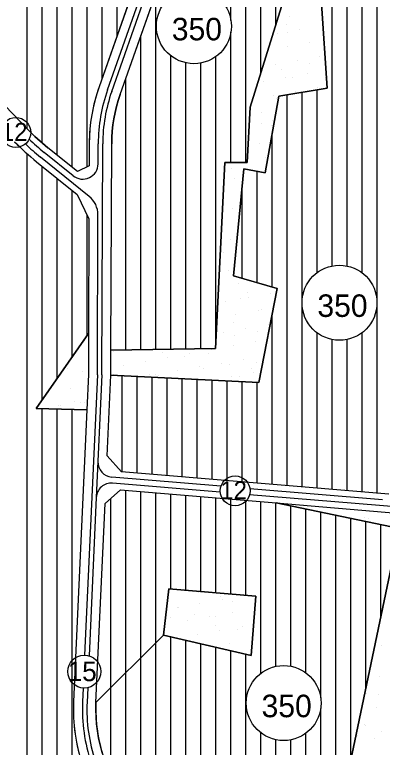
# Model space of a CAD drawing. Extents: x 419109 to 421295, y 4452223 to 4457798.
# Drawn here: x 420679.4 to 420924.6, y 4452952.7 to 4453441.3 of the extents above; entities that cross this region are included whole.
import ezdxf

# ---------------------------------------------------------------- set-up
doc = ezdxf.new("R2010")
doc.units = 0
for name, color, linetype in [('ADA', 7, 'Continuous'), ('ADAKENARI', 7, 'Continuous'), ('Default', 7, 'Continuous'), ('KALDIRIM', 7, 'Continuous'), ('KD_DAIRE', 7, 'Continuous'), ('KD_YGEN', 7, 'Continuous'), ('PL_AYA_PARK_DINLENME', 7, 'Continuous'), ('PL_KON_MEV_350', 7, 'Continuous'), ('SM_DAIRE', 7, 'Continuous'), ('SM_TAKS', 7, 'Continuous'), ('TR_ORTAYOGUNKONUT', 7, 'Continuous'), ('TR_PARKALANI', 7, 'Continuous')]:
    doc.layers.add(name, color=color, linetype=linetype)

# ---------------------------------------------------------------- blocks, each defined once
blk = doc.blocks.new('POINT_DISPLAY')
at = {"layer": 'Default'}
blk.add_line((0, 0), (0, 0), dxfattribs=at)

msp = doc.modelspace()

# ---------------------------------------------------------------- linework, layer by layer
at = {"layer": 'ADA'}
for p, q in [((420901.28, 4453588.27), (420836.55, 4453379.63)), ((420887.76, 4453392.3), (420884.07, 4453448.79)), ((420855.56, 4453387.02), (420887.76, 4453392.3)), ((420846.58, 4453335.82), (420855.56, 4453387.02)), ((420836.55, 4453379.63), (420834.44, 4453342.68)), ((420819.66, 4453342.68), (420813.32, 4453218.61)), ((420834.44, 4453342.68), (420819.66, 4453342.68)), ((420825.47, 4453267.18), (420832.33, 4453338.45)), ((420832.33, 4453338.45), (420846.58, 4453335.82)), ((420854.5, 4453258.74), (420825.47, 4453267.18)), ((420842.36, 4453195.91), (420854.5, 4453258.74)), ((420728.7, 4453228.73), (420693.82, 4453178.65)), ((420813.32, 4453218.61), (420743.66, 4453217.53)), ((420743.6, 4453200.88), (420842.36, 4453195.91)), ((420693.82, 4453178.65), (420727.53, 4453177.73)), ((420936.03, 4453098.7), (420853.73, 4453115.66)), ((420903.28, 4452943.11), (420930.77, 4453073.67)), ((420778.66, 4453027.49), (420782.22, 4453058.47)), ((420782.22, 4453058.47), (420840.26, 4453053.48)), ((420840.26, 4453053.48), (420837.05, 4453013.96)), ((420837.05, 4453013.96), (420778.66, 4453027.49))]:
    msp.add_line(p, q, dxfattribs=at)
at = {"layer": 'ADAKENARI'}
for p, q in [((420814.22, 4453615.89), (420735.68, 4453393.04)), ((420749.83, 4453388.06), (420826.37, 4453605.23)), ((420688.05, 4453364.9), (420668.06, 4453385.54)), ((420729.14, 4453355.22), (420729.09, 4453340.38)), ((420743.66, 4453217.53), (420744.14, 4453355.17)), ((420721.27, 4453336.66), (420701.59, 4453352.54)), ((420694.05, 4453343.2), (420721.22, 4453321.28)), ((420729.09, 4453340.38), (420721.27, 4453336.66)), ((420721.22, 4453321.28), (420728.97, 4453305)), ((420728.97, 4453305), (420728.7, 4453228.73)), ((420728.7, 4453228.73), (420728.6, 4453201.25)), ((420743.6, 4453200.88), (420743.66, 4453217.53)), ((420728.6, 4453201.25), (420727.53, 4453177.73)), ((420741.16, 4453147.16), (420743.6, 4453200.88)), ((420727.53, 4453177.73), (420718.69, 4452983.19)), ((420750.67, 4453136.33), (420741.16, 4453147.16)), ((420928.94, 4453121.4), (420750.67, 4453136.33)), ((420739.7, 4453115.18), (420750.12, 4453124.34)), ((420750.12, 4453124.34), (420853.73, 4453115.66)), ((420733.67, 4452982.51), (420739.7, 4453115.18)), ((420853.73, 4453115.66), (420934.35, 4453108.91))]:
    msp.add_line(p, q, dxfattribs=at)
for centre, radius, start, end in [((420844.14, 4453354.81), 115, 160.5853, 179.7987), ((420844.14, 4453354.81), 100, 160.5853, 179.7987), ((420795.79, 4453469.27), 150, 224.0912, 231.0974), ((420795.79, 4453469.27), 162, 224.0912, 231.0974), ((420833.57, 4452977.97), 115, 177.3972, 199.0423), ((420833.57, 4452977.97), 100, 177.3972, 199.0423)]:
    msp.add_arc(centre, radius, start, end, dxfattribs=at)
at = {"layer": 'KALDIRIM'}
for p, q in [((420741.34, 4453391.05), (420765.66, 4453460.05)), ((420744.17, 4453390.05), (420768.35, 4453458.65)), ((420735.1, 4453341.79), (420735.14, 4453355.2)), ((420737.6, 4453201.03), (420738.14, 4453355.19)), ((420718.39, 4453333.84), (420699.08, 4453349.43)), ((420729.12, 4453320.04), (420696.56, 4453346.32)), ((420734.6, 4453201.1), (420734.98, 4453307.74)), ((420734.6, 4453201.1), (420726.1, 4453014.19)), ((420737.6, 4453201.03), (420733.88, 4453119.29)), ((420816.95, 4453126.77), (420744.13, 4453132.87)), ((420816.51, 4453122.79), (420744.71, 4453128.8)), ((420924.61, 4453117.75), (420836.36, 4453125.14)), ((420733.88, 4453119.29), (420729.09, 4453013.72)), ((420936.62, 4453112.73), (420836.13, 4453121.15)), ((420725.11, 4452992.22), (420724.68, 4452982.92)), ((420728.12, 4452992.42), (420727.68, 4452982.78))]:
    msp.add_line(p, q, dxfattribs=at)
for centre, radius, start, end in [((420844.14, 4453354.81), 109, 160.5853, 179.7987), ((420844.14, 4453354.81), 106, 160.5853, 179.7987), ((420795.79, 4453469.27), 158, 226.2962, 231.0974), ((420795.79, 4453469.27), 154, 226.1558, 231.0974), ((420724.84, 4453341.83), 10.26, 231.0974, 359.7987), ((420719.25, 4453307.8), 15.73, 359.7987, 51.0974), ((420744.97, 4453142.83), 10, 177.3972, 265.212), ((420743.87, 4453118.84), 10, 85.212, 177.3972), ((420833.57, 4452977.97), 109, 177.3972, 199.0423), ((420833.57, 4452977.97), 106, 177.3972, 199.0423)]:
    msp.add_arc(centre, radius, start, end, dxfattribs=at)
at = {"layer": 'KD_DAIRE'}
for centre, radius in [((420680.18, 4453362.7), 10), ((420826.47, 4453123.71), 10), ((420725.89, 4453003.19), 11)]:
    msp.add_circle(centre, radius, dxfattribs=at)
at = {"layer": 'PL_AYA_PARK_DINLENME'}
for points in [[(420836.55, 4453379.63), (420901.28, 4453588.27), (420939.56, 4453574.15), (420903.07, 4453570.75), (420888.82, 4453532.21), (420893.04, 4453450.38), (420884.07, 4453448.79), (420887.76, 4453392.3), (420855.56, 4453387.02), (420846.58, 4453335.82), (420832.33, 4453338.45), (420825.47, 4453267.18), (420854.5, 4453258.74), (420842.36, 4453195.91), (420743.6, 4453200.88), (420743.66, 4453217.53), (420813.32, 4453218.61), (420819.66, 4453342.68), (420834.44, 4453342.68)], [(420727.53, 4453177.73), (420693.82, 4453178.65), (420728.7, 4453228.73), (420728.6, 4453201.25)], [(420936.03, 4453098.7), (420853.73, 4453115.66), (420934.35, 4453108.91), (420949.33, 4453099.42), (420951.61, 4453095.49)], [(420903.28, 4452943.11), (420930.77, 4453073.67), (420951.34, 4453069.86), (420962.86, 4453076.1), (420986.96, 4453034.57), (420939.24, 4453034.97), (420937.46, 4452935.63)], [(420837.05, 4453013.96), (420778.66, 4453027.49), (420782.22, 4453058.47), (420840.26, 4453053.48)]]:
    msp.add_lwpolyline(points, close=True, dxfattribs=at)
at = {"layer": 'PL_KON_MEV_350'}
for points in [[(420814.22, 4453615.89), (420735.68, 4453393.04), (420734.17, 4453388.46), (420732.86, 4453383.82), (420731.74, 4453379.14), (420730.82, 4453374.4), (420730.1, 4453369.64), (420729.58, 4453364.85), (420729.26, 4453360.04), (420729.14, 4453355.22), (420729.09, 4453340.38), (420721.27, 4453336.66), (420701.59, 4453352.54), (420699.81, 4453353.99), (420698.06, 4453355.48), (420696.34, 4453356.98), (420694.63, 4453358.52), (420692.95, 4453360.07), (420691.29, 4453361.66), (420689.66, 4453363.27), (420688.05, 4453364.9), (420668.06, 4453385.54)], [(420928.94, 4453121.4), (420750.67, 4453136.33), (420741.16, 4453147.16), (420743.6, 4453200.88), (420842.36, 4453195.91), (420854.5, 4453258.74), (420825.47, 4453267.18), (420832.33, 4453338.45), (420846.58, 4453335.82), (420855.56, 4453387.02), (420887.76, 4453392.3), (420884.07, 4453448.79)], [(420679.43, 4453356.55), (420681.17, 4453354.79), (420682.93, 4453353.05), (420684.72, 4453351.34), (420686.54, 4453349.65), (420688.38, 4453348), (420690.25, 4453346.37), (420692.14, 4453344.77), (420694.05, 4453343.2), (420721.22, 4453321.28), (420728.97, 4453305), (420728.7, 4453228.73), (420693.82, 4453178.65), (420727.53, 4453177.73), (420718.69, 4452983.19), (420718.57, 4452977.76), (420718.71, 4452972.33), (420719.1, 4452966.91), (420719.75, 4452961.52), (420720.65, 4452956.17), (420721.81, 4452950.86)]]:
    msp.add_lwpolyline(points, dxfattribs=at)
for points in [[(420749.83, 4453388.06), (420826.37, 4453605.23), (420839.08, 4453611.2), (420901.28, 4453588.27), (420836.55, 4453379.63), (420834.44, 4453342.68), (420819.66, 4453342.68), (420813.32, 4453218.61), (420743.66, 4453217.53), (420744.14, 4453355.17), (420744.24, 4453359.36), (420744.52, 4453363.54), (420744.98, 4453367.71), (420745.6, 4453371.85), (420746.4, 4453375.96), (420747.38, 4453380.04), (420748.52, 4453384.07)], [(420853.73, 4453115.66), (420936.03, 4453098.7), (420930.77, 4453073.67), (420903.28, 4452943.11), (420896.71, 4452915.75), (420797.89, 4452939.65), (420762.79, 4452946.51), (420739.04, 4452945.34), (420737.61, 4452949.84), (420736.39, 4452954.4), (420735.38, 4452959.01), (420734.6, 4452963.67), (420734.03, 4452968.36), (420733.69, 4452973.07), (420733.57, 4452977.79), (420733.67, 4452982.51), (420778.66, 4453027.49), (420837.05, 4453013.96), (420840.26, 4453053.48), (420782.22, 4453058.47), (420778.66, 4453027.49), (420733.67, 4452982.51), (420739.7, 4453115.18), (420750.12, 4453124.34)]]:
    msp.add_lwpolyline(points, close=True, dxfattribs=at)
at = {"layer": 'SM_DAIRE'}
for centre in [(420798.96, 4453433.58), (420896.04, 4453249.15), (420858.83, 4452982.2)]:
    msp.add_circle(centre, 25, dxfattribs=at)
at = {"layer": 'TR_ORTAYOGUNKONUT'}
for p, q in [((420747.76, 4453427.31), (420747.76, 4453678.84)), ((420737.76, 4453398.94), (420737.76, 4453666.77)), ((420833.66, 4453342.68), (420833.66, 4453608.65)), ((420843.66, 4453402.54), (420843.66, 4453609.51)), ((420853.66, 4453434.77), (420853.66, 4453605.82)), ((420823.66, 4453437.48), (420823.66, 4453597.54)), ((420911.16, 4453269.06), (420911.16, 4453571.5)), ((420921.16, 4453122.05), (420921.16, 4453572.43)), ((420901.16, 4453273.62), (420901.16, 4453565.57)), ((420687.76, 4453365.21), (420687.76, 4453496.6)), ((420727.76, 4453339.74), (420727.76, 4453499.32)), ((420697.76, 4453355.74), (420697.76, 4453489.53)), ((420707.76, 4453347.56), (420707.76, 4453487.88)), ((420717.76, 4453339.49), (420717.76, 4453490.42)), ((420773.66, 4453218), (420773.66, 4453455.67)), ((420891.16, 4453273.67), (420891.16, 4453450.04)), ((420763.66, 4453217.84), (420763.66, 4453427.3)), ((420823.66, 4453342.68), (420823.66, 4453429.68)), ((420783.66, 4453218.15), (420783.66, 4453413.82)), ((420813.66, 4453225.18), (420813.66, 4453413.36)), ((420793.66, 4453218.31), (420793.66, 4453409.15)), ((420803.66, 4453218.46), (420803.66, 4453409.03)), ((420753.66, 4453217.69), (420753.66, 4453398.92)), ((420861.16, 4453127.08), (420861.16, 4453387.94)), ((420871.16, 4453251.6), (420871.16, 4453389.58)), ((420881.16, 4453269.24), (420881.16, 4453391.22)), ((420851.16, 4453259.71), (420851.16, 4453361.92)), ((420687.83, 4452920.69), (420687.83, 4453348.49)), ((420697.83, 4453184.41), (420697.83, 4453340.15)), ((420841.16, 4453262.62), (420841.16, 4453336.82)), ((420707.83, 4453198.77), (420707.83, 4453332.08)), ((420831.16, 4453265.53), (420831.16, 4453326.29)), ((420717.83, 4453213.13), (420717.83, 4453324.01)), ((420727.83, 4453227.49), (420727.83, 4453307.38)), ((420871.16, 4453126.24), (420871.16, 4453246.69)), ((420851.16, 4453127.92), (420851.16, 4453241.43)), ((420881.16, 4453125.4), (420881.16, 4453229.06)), ((420911.16, 4453122.89), (420911.16, 4453229.24)), ((420891.16, 4453124.57), (420891.16, 4453224.63)), ((420901.16, 4453123.73), (420901.16, 4453224.68)), ((420751.16, 4453136.29), (420751.16, 4453200.5)), ((420761.16, 4453135.45), (420761.16, 4453200)), ((420771.16, 4453134.62), (420771.16, 4453199.5)), ((420781.16, 4453133.78), (420781.16, 4453198.99)), ((420791.16, 4453132.94), (420791.16, 4453198.49)), ((420801.16, 4453132.1), (420801.16, 4453197.99)), ((420811.16, 4453131.27), (420811.16, 4453197.48)), ((420821.16, 4453130.43), (420821.16, 4453196.98)), ((420831.16, 4453129.59), (420831.16, 4453196.48)), ((420841.16, 4453128.75), (420841.16, 4453195.97)), ((420697.83, 4452918.49), (420697.83, 4453178.54)), ((420707.83, 4452916.28), (420707.83, 4453178.27)), ((420717.83, 4452914.09), (420717.83, 4453177.99)), ((420753.57, 4452946.06), (420753.57, 4453124.05)), ((420763.57, 4452946.36), (420763.57, 4453123.21)), ((420773.57, 4452944.4), (420773.57, 4453122.37)), ((420783.57, 4453058.35), (420783.57, 4453121.54)), ((420793.57, 4453057.49), (420793.57, 4453120.7)), ((420803.57, 4453056.63), (420803.57, 4453119.86)), ((420743.57, 4452945.56), (420743.57, 4453118.58)), ((420813.57, 4453055.77), (420813.57, 4453119.02)), ((420823.57, 4453054.91), (420823.57, 4453118.18)), ((420833.57, 4453054.06), (420833.57, 4453117.35)), ((420843.57, 4453002), (420843.57, 4453116.51)), ((420853.57, 4453006.64), (420853.57, 4453115.67)), ((420863.57, 4453006.74), (420863.57, 4453113.63)), ((420873.57, 4453002.39), (420873.57, 4453111.57)), ((420883.57, 4452985.77), (420883.57, 4453109.51)), ((420893.57, 4452921.26), (420893.57, 4453107.45)), ((420903.57, 4452944.49), (420903.57, 4453105.39)), ((420913.57, 4452991.99), (420913.57, 4453103.33)), ((420923.57, 4453039.49), (420923.57, 4453101.27)), ((420783.57, 4452942.45), (420783.57, 4453026.35)), ((420793.57, 4452940.49), (420793.57, 4453024.03)), ((420803.57, 4452938.27), (420803.57, 4453021.72)), ((420813.57, 4452935.85), (420813.57, 4453019.4)), ((420823.57, 4452933.44), (420823.57, 4453017.08)), ((420833.57, 4452931.02), (420833.57, 4453014.77)), ((420883.57, 4452928.34), (420883.57, 4452978.63)), ((420843.57, 4452928.6), (420843.57, 4452962.39)), ((420873.57, 4452930), (420873.57, 4452962.01)), ((420853.57, 4452926.18), (420853.57, 4452957.76)), ((420863.57, 4452927.47), (420863.57, 4452957.65))]:
    msp.add_line(p, q, dxfattribs=at)

# ---------------------------------------------------------------- block references
at = {"layer": 'TR_PARKALANI', "xscale": 0.1, "yscale": 0.10000000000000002}
for p in [(420862.97, 4453440.35), (420860.65, 4453434.93), (420884.4, 4453433.98), (420854.86, 4453428.77), (420861.53, 4453429.47), (420869.63, 4453431.37), (420885, 4453429.25), (420876.29, 4453422.39), (420861.52, 4453419.79), (420882.95, 4453413.41), (420853.4, 4453408.21), (420868.18, 4453410.81), (420876.1, 4453408.74), (420857.19, 4453404.85), (420860.06, 4453399.23), (420864.61, 4453399.09), (420874.84, 4453401.83), (420886.73, 4453399.64), (420845.29, 4453396.62), (420881.5, 4453392.85), (420866.73, 4453390.25), (420851.95, 4453387.64), (420853.72, 4453385.15), (420843.84, 4453376.06), (420844.23, 4453368.94), (420851.11, 4453370.38), (420835.73, 4453364.47), (420850.5, 4453367.08), (420842.39, 4453355.49), (420846.77, 4453345.76), (420823.84, 4453338.78), (420826.17, 4453332.32), (420824.72, 4453311.76), (420823.27, 4453291.19), (420818.91, 4453282.42), (420821.81, 4453270.63), (420828.47, 4453261.65), (420834.37, 4453256.23), (420830.27, 4453252.21), (420835.14, 4453252.67), (420849.91, 4453255.27), (420820.36, 4453250.07), (420841.8, 4453243.69), (420844.18, 4453244.68), (420827.02, 4453241.09), (420825.47, 4453235.71), (420833.68, 4453232.11), (420848.46, 4453234.71), (420818.91, 4453229.5), (420825.93, 4453227.59), (420841.57, 4453229.9), (420726.27, 4453224.07), (420813.98, 4453226.07), (420840.34, 4453223.13), (420810.8, 4453217.92), (420825.57, 4453220.52), (420718.16, 4453212.48), (420745.05, 4453216.48), (420778.14, 4453215.7), (420781.26, 4453212.71), (420792.92, 4453213.1), (420796.03, 4453215.31), (420808.56, 4453215.42), (420751.71, 4453207.5), (420766.48, 4453210.1), (420817.46, 4453208.94), (420822.46, 4453207.89), (420832.23, 4453211.54), (420840.93, 4453209.52), (420714.46, 4453205.05), (420724.82, 4453203.5), (420728.37, 4453203.92), (420787.92, 4453203.73), (420802.69, 4453206.33), (420805.09, 4453205.55), (420837.23, 4453205.28), (420838.89, 4453202.56), (420710.04, 4453200.9), (420728.37, 4453197.52), (420745.13, 4453201.22), (420769.25, 4453201.59), (420773.14, 4453201.12), (420775.54, 4453200.93), (420824.12, 4453199.96), (420829.44, 4453199.88), (420701.93, 4453189.31), (420716.7, 4453191.92), (420719.47, 4453183.41), (420723.37, 4453182.94), (420725.76, 4453182.75), (420708.59, 4453180.33), (420710.12, 4453180.43), (420891.39, 4453112.28), (420912.82, 4453105.91), (420915.23, 4453105.13), (420801.9, 4453056.05), (420816.68, 4453053.45), (420817.77, 4453051.32), (420832.54, 4453053.92), (420788.22, 4453046.11), (420802.99, 4453048.71), (420824.7, 4453049.8), (420788.86, 4453045.83), (420799.3, 4453041.28), (420824.43, 4453042.34), (420839.2, 4453044.94), (420783.66, 4453038.96), (420794.88, 4453037.13), (420809.66, 4453039.73), (420813.21, 4453040.15), (420780.11, 4453034.52), (420813.2, 4453033.75), (420831.09, 4453033.36), (420801.54, 4453028.15), (420816.32, 4453030.75), (420827.98, 4453031.15), (420822.98, 4453021.77), (420837.75, 4453024.38), (420923.85, 4453020.49), (420922.4, 4452999.93), (420914.29, 4452988.34), (420922.37, 4452988.02), (420912.62, 4452985.25), (420920.95, 4452979.36), (420912.84, 4452967.78), (420913.48, 4452967.5), (420923.92, 4452962.95), (420908.28, 4452960.63), (420919.5, 4452958.8)]:
    msp.add_blockref('POINT_DISPLAY', p, dxfattribs=at)

# ---------------------------------------------------------------- texts
at = {"layer": 'KD_YGEN'}
for s, height, p in [('12', 12, (420670.21, 4453357.09)), ('12', 12, (420816.49, 4453118.09)), ('15', 13, (420714.79, 4452996.8))]:
    msp.add_text(s, height=height, dxfattribs=at).set_placement(p)
at = {"layer": 'SM_TAKS'}
for p in [(420784.22, 4453424.14), (420881.3, 4453239.7), (420844.09, 4452972.75)]:
    msp.add_text('350', height=15, dxfattribs=at).set_placement(p)

doc.saveas('drawing.dxf')
